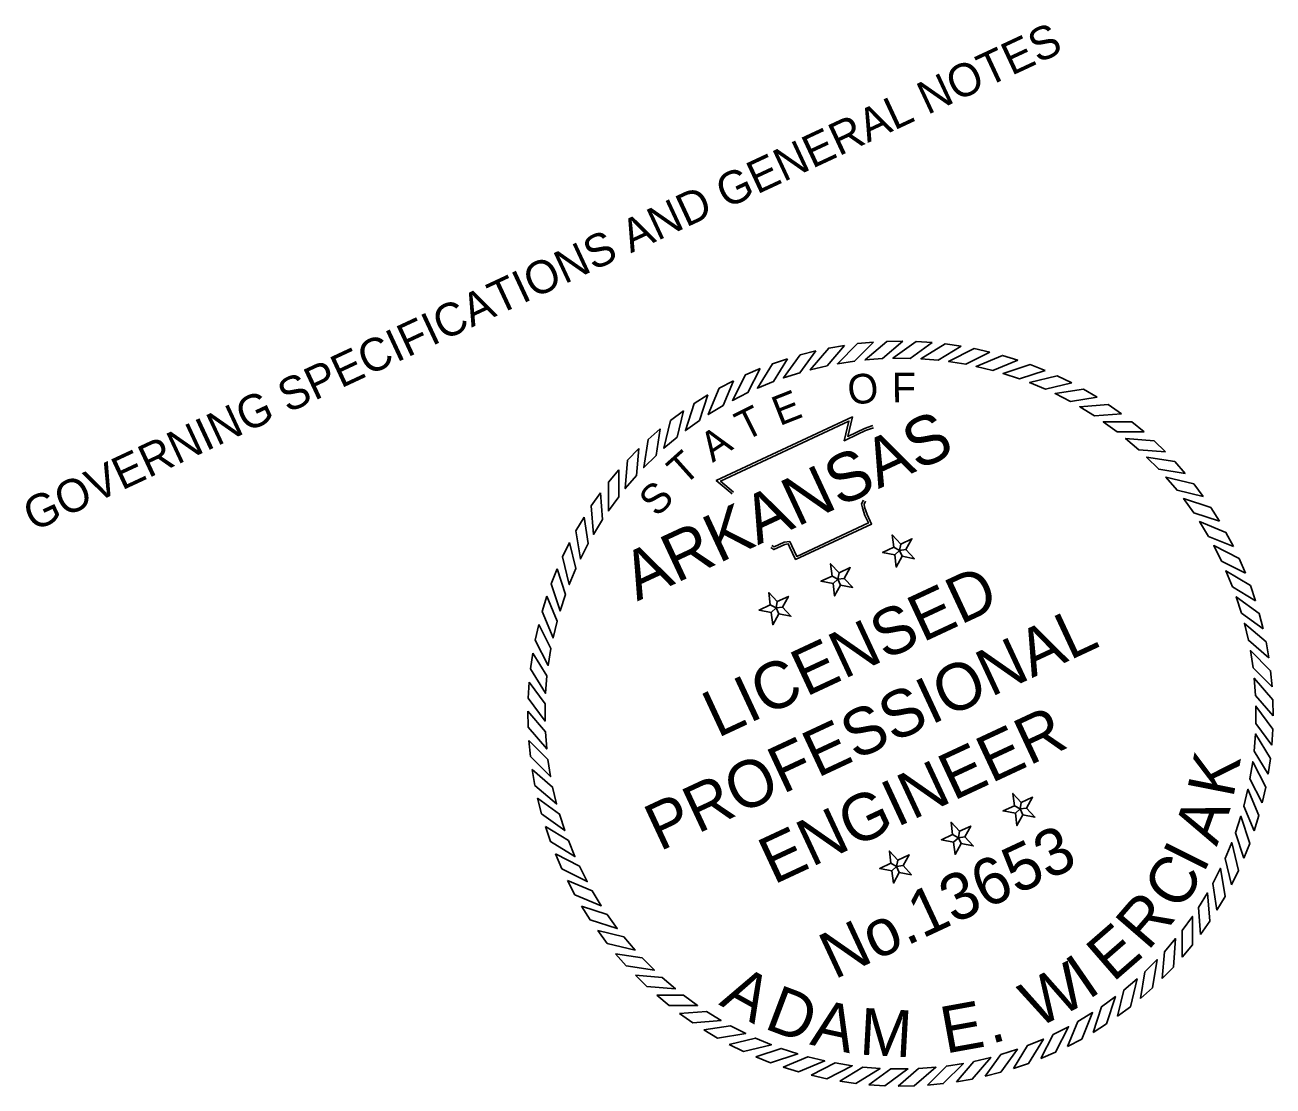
# Model space of a CAD drawing. Extents: x 756658 to 763719, y 1656413 to 1661090.
# Drawn here: x 762588.8 to 762989.5, y 1660427.5 to 1660768.4 of the extents above; entities that cross this region are included whole.
import ezdxf

# ---------------------------------------------------------------- set-up
doc = ezdxf.new("R2010")
doc.units = 0
doc.layers.add('1', color=7, linetype='Continuous')
doc.layers.add('G-ANNO-STMP-AEW', color=7, linetype='Continuous')

msp = doc.modelspace()

# ---------------------------------------------------------------- linework, layer by layer
at = {"layer": 'G-ANNO-STMP-AEW'}
for points in [[(762861.26, 1660666.49), (762856.14, 1660666), (762849.66, 1660659.52), (762855.15, 1660660.37)], [(762870.65, 1660666.79), (762865.51, 1660666.72), (762858.54, 1660660.76), (762864.08, 1660661.18)], [(762880.04, 1660666.37), (762874.9, 1660666.69), (762867.48, 1660661.3), (762873.04, 1660661.28)], [(762842.71, 1660663.67), (762837.72, 1660662.39), (762832.33, 1660654.97), (762837.62, 1660656.67)], [(762851.93, 1660665.44), (762846.86, 1660664.56), (762840.91, 1660657.59), (762846.32, 1660658.87)], [(762889.36, 1660665.2), (762884.26, 1660665.93), (762876.45, 1660661.14), (762881.99, 1660660.69)], [(762898.56, 1660663.31), (762893.54, 1660664.44), (762885.37, 1660660.27), (762890.86, 1660659.39)], [(762833.65, 1660661.17), (762828.78, 1660659.51), (762823.99, 1660651.69), (762829.13, 1660653.8)], [(762907.58, 1660660.71), (762902.67, 1660662.22), (762894.2, 1660658.71), (762899.6, 1660657.4)], [(762916.37, 1660657.4), (762911.59, 1660659.3), (762902.87, 1660656.46), (762908.15, 1660654.73)], [(762824.82, 1660657.98), (762820.09, 1660655.94), (762815.93, 1660647.77), (762820.89, 1660650.27)], [(762924.88, 1660653.41), (762920.26, 1660655.68), (762911.35, 1660653.54), (762916.47, 1660651.39)], [(762816.26, 1660654.1), (762811.71, 1660651.69), (762808.2, 1660643.22), (762812.95, 1660646.11)], [(762933.05, 1660648.77), (762928.62, 1660651.39), (762919.56, 1660649.96), (762924.51, 1660647.42)], [(762808.04, 1660649.56), (762803.69, 1660646.81), (762800.86, 1660638.09), (762805.36, 1660641.34)], [(762940.82, 1660643.5), (762936.62, 1660646.46), (762927.48, 1660645.74), (762932.21, 1660642.82)], [(762800.19, 1660644.39), (762796.08, 1660641.31), (762793.94, 1660632.39), (762798.18, 1660635.99)], [(762792.78, 1660638.62), (762788.92, 1660635.22), (762787.48, 1660626.17), (762791.43, 1660630.08)], [(762948.16, 1660637.64), (762944.2, 1660640.92), (762935.03, 1660640.92), (762939.52, 1660637.64)], [(762955.02, 1660631.22), (762951.33, 1660634.8), (762942.19, 1660635.52), (762946.4, 1660631.9)], [(762785.84, 1660632.29), (762782.26, 1660628.6), (762781.54, 1660619.46), (762785.16, 1660623.67)], [(762961.35, 1660624.28), (762957.95, 1660628.14), (762948.9, 1660629.58), (762952.81, 1660625.64)], [(762779.42, 1660625.43), (762776.14, 1660621.47), (762776.14, 1660612.3), (762779.42, 1660616.79)], [(762967.12, 1660616.87), (762964.04, 1660620.99), (762955.12, 1660623.13), (762958.72, 1660618.89)], [(762773.56, 1660618.09), (762770.6, 1660613.89), (762771.32, 1660604.75), (762774.24, 1660609.48)], [(762972.29, 1660609.03), (762969.54, 1660613.37), (762960.82, 1660616.21), (762964.07, 1660611.7)], [(762768.29, 1660610.32), (762765.67, 1660605.89), (762767.11, 1660596.83), (762769.65, 1660601.78)], [(762976.83, 1660600.8), (762974.42, 1660605.35), (762965.95, 1660608.86), (762968.84, 1660604.11)], [(762869.59, 1660599.59), (762869.99, 1660601.64), (762867.28, 1660604.54), (762867.76, 1660600.6)], [(762869.59, 1660599.59), (762871.66, 1660599.84), (762873.59, 1660603.32), (762869.99, 1660601.64)], [(762763.65, 1660602.15), (762761.39, 1660597.53), (762763.53, 1660588.62), (762765.67, 1660593.74)], [(762869.59, 1660599.59), (762867.76, 1660600.6), (762864.16, 1660598.92), (762868.06, 1660598.16)], [(762869.59, 1660599.59), (762868.06, 1660598.16), (762868.55, 1660594.22), (762870.47, 1660597.69)], [(762869.59, 1660599.59), (762870.47, 1660597.69), (762874.37, 1660596.93), (762871.66, 1660599.84)], [(762980.71, 1660592.25), (762978.67, 1660596.97), (762970.5, 1660601.13), (762973, 1660596.17)], [(762849.76, 1660590.34), (762850.16, 1660592.39), (762847.45, 1660595.3), (762847.94, 1660591.35)], [(762759.66, 1660593.65), (762757.77, 1660588.86), (762760.6, 1660580.14), (762762.34, 1660585.42)], [(762849.76, 1660590.34), (762847.94, 1660591.35), (762844.34, 1660589.67), (762848.24, 1660588.92)], [(762849.76, 1660590.34), (762848.24, 1660588.92), (762848.72, 1660584.97), (762850.65, 1660588.45)], [(762849.76, 1660590.34), (762851.84, 1660590.6), (762853.76, 1660594.07), (762850.16, 1660592.39)], [(762849.76, 1660590.34), (762850.65, 1660588.45), (762854.55, 1660587.69), (762851.84, 1660590.6)], [(762983.9, 1660583.41), (762982.24, 1660588.28), (762974.42, 1660593.07), (762976.53, 1660587.93)], [(762756.36, 1660584.85), (762754.84, 1660579.94), (762758.35, 1660571.47), (762759.67, 1660576.87)], [(762829.94, 1660581.1), (762830.34, 1660583.15), (762827.63, 1660586.05), (762828.11, 1660582.11)], [(762829.94, 1660581.1), (762832.01, 1660581.35), (762833.94, 1660584.83), (762830.34, 1660583.15)], [(762986.4, 1660574.36), (762985.12, 1660579.34), (762977.7, 1660584.73), (762979.4, 1660579.44)], [(762829.94, 1660581.1), (762828.11, 1660582.11), (762824.51, 1660580.43), (762828.41, 1660579.67)], [(762829.94, 1660581.1), (762828.41, 1660579.67), (762828.9, 1660575.73), (762830.82, 1660579.2)], [(762829.94, 1660581.1), (762830.82, 1660579.2), (762834.72, 1660578.44), (762832.01, 1660581.35)], [(762753.75, 1660575.83), (762752.63, 1660570.81), (762756.79, 1660562.64), (762757.68, 1660568.13)], [(762988.17, 1660565.13), (762987.29, 1660570.2), (762980.32, 1660576.16), (762981.6, 1660570.75)], [(762751.86, 1660566.63), (762751.13, 1660561.54), (762755.92, 1660553.72), (762756.38, 1660559.26)], [(762989.21, 1660555.8), (762988.73, 1660560.92), (762982.25, 1660567.4), (762983.1, 1660561.91)], [(762989.52, 1660546.41), (762989.45, 1660551.55), (762983.49, 1660558.53), (762983.91, 1660552.98)], [(762750.7, 1660557.31), (762750.37, 1660552.17), (762755.76, 1660544.75), (762755.78, 1660550.31)], [(762750.27, 1660547.92), (762750.35, 1660542.78), (762756.3, 1660535.81), (762755.88, 1660541.35)], [(762989.1, 1660537.03), (762989.42, 1660542.16), (762984.03, 1660549.58), (762984.01, 1660544.02)], [(762750.58, 1660538.54), (762751.06, 1660533.41), (762757.54, 1660526.93), (762756.69, 1660532.42)], [(762987.93, 1660527.71), (762988.66, 1660532.8), (762983.87, 1660540.62), (762983.42, 1660535.08)], [(762986.04, 1660518.51), (762987.17, 1660523.53), (762983, 1660531.7), (762982.12, 1660526.21)], [(762751.62, 1660529.2), (762752.51, 1660524.13), (762759.48, 1660518.18), (762758.2, 1660523.59)], [(762983.44, 1660509.48), (762984.95, 1660514.4), (762981.44, 1660522.87), (762980.13, 1660517.47)], [(762753.4, 1660519.98), (762754.67, 1660514.99), (762762.09, 1660509.6), (762760.39, 1660514.89)], [(762908.3, 1660516.57), (762908.7, 1660518.62), (762905.99, 1660521.52), (762906.48, 1660517.58)], [(762908.3, 1660516.57), (762910.38, 1660516.82), (762912.3, 1660520.3), (762908.7, 1660518.62)], [(762908.3, 1660516.57), (762906.48, 1660517.58), (762902.87, 1660515.9), (762906.78, 1660515.14)], [(762908.3, 1660516.57), (762906.78, 1660515.14), (762907.26, 1660511.2), (762909.19, 1660514.67)], [(762908.3, 1660516.57), (762909.19, 1660514.67), (762913.09, 1660513.91), (762910.38, 1660516.82)], [(762980.13, 1660500.69), (762982.02, 1660505.47), (762979.19, 1660514.19), (762977.46, 1660508.91)], [(762755.89, 1660510.92), (762757.55, 1660506.05), (762765.37, 1660501.26), (762763.26, 1660506.4)], [(762888.48, 1660507.32), (762888.88, 1660509.37), (762886.17, 1660512.28), (762886.65, 1660508.33)], [(762888.48, 1660507.32), (762890.55, 1660507.58), (762892.48, 1660511.05), (762888.88, 1660509.37)], [(762888.48, 1660507.32), (762886.65, 1660508.33), (762883.05, 1660506.65), (762886.95, 1660505.9)], [(762888.48, 1660507.32), (762886.95, 1660505.9), (762887.43, 1660501.95), (762889.36, 1660505.43)], [(762888.48, 1660507.32), (762889.36, 1660505.43), (762893.26, 1660504.67), (762890.55, 1660507.58)], [(762759.09, 1660502.09), (762761.13, 1660497.36), (762769.3, 1660493.2), (762766.79, 1660498.16)], [(762868.65, 1660498.08), (762869.05, 1660500.13), (762866.34, 1660503.03), (762866.82, 1660499.09)], [(762976.14, 1660492.18), (762978.41, 1660496.8), (762976.27, 1660505.72), (762974.12, 1660500.59)], [(762868.65, 1660498.08), (762866.82, 1660499.09), (762863.22, 1660497.41), (762867.12, 1660496.65)], [(762868.65, 1660498.08), (762867.12, 1660496.65), (762867.61, 1660492.71), (762869.53, 1660496.18)], [(762868.65, 1660498.08), (762870.72, 1660498.33), (762872.65, 1660501.81), (762869.05, 1660500.13)], [(762868.65, 1660498.08), (762869.53, 1660496.18), (762873.43, 1660495.42), (762870.72, 1660498.33)], [(762971.5, 1660484.02), (762974.12, 1660488.44), (762972.69, 1660497.5), (762970.15, 1660492.56)], [(762762.96, 1660493.53), (762765.37, 1660488.98), (762773.84, 1660485.47), (762770.95, 1660490.22)], [(762966.23, 1660476.24), (762969.19, 1660480.45), (762968.47, 1660489.59), (762965.55, 1660484.86)], [(762767.5, 1660485.31), (762770.26, 1660480.96), (762778.98, 1660478.13), (762775.72, 1660482.64)], [(762960.37, 1660468.9), (762963.65, 1660472.86), (762963.65, 1660482.03), (762960.37, 1660477.55)], [(762772.67, 1660477.46), (762775.76, 1660473.35), (762784.67, 1660471.21), (762781.08, 1660475.45)], [(762953.95, 1660462.04), (762957.53, 1660465.74), (762958.25, 1660474.88), (762954.63, 1660470.66)], [(762778.44, 1660470.05), (762781.84, 1660466.19), (762790.9, 1660464.76), (762786.98, 1660468.7)], [(762947.01, 1660455.71), (762950.87, 1660459.11), (762952.31, 1660468.17), (762948.37, 1660464.25)], [(762784.77, 1660463.11), (762788.46, 1660459.53), (762797.61, 1660458.81), (762793.39, 1660462.43)], [(762939.6, 1660449.94), (762943.72, 1660453.03), (762945.86, 1660461.94), (762941.62, 1660458.35)], [(762791.63, 1660456.69), (762795.59, 1660453.41), (762804.76, 1660453.41), (762800.28, 1660456.69)], [(762931.76, 1660444.77), (762936.1, 1660447.53), (762938.94, 1660456.25), (762934.43, 1660453)], [(762798.97, 1660450.83), (762803.18, 1660447.87), (762812.32, 1660448.59), (762807.59, 1660451.51)], [(762923.53, 1660440.23), (762928.08, 1660442.64), (762931.59, 1660451.11), (762926.84, 1660448.22)], [(762806.75, 1660445.56), (762811.17, 1660442.94), (762820.23, 1660444.38), (762815.29, 1660446.92)], [(762914.98, 1660436.36), (762919.7, 1660438.4), (762923.86, 1660446.57), (762918.9, 1660444.06)], [(762814.91, 1660440.92), (762819.53, 1660438.66), (762828.45, 1660440.8), (762823.32, 1660442.94)], [(762906.14, 1660433.16), (762911.01, 1660434.82), (762915.8, 1660442.64), (762910.66, 1660440.53)], [(762823.42, 1660436.94), (762828.2, 1660435.04), (762836.92, 1660437.87), (762831.64, 1660439.61)], [(762897.09, 1660430.67), (762902.07, 1660431.95), (762907.46, 1660439.36), (762902.17, 1660437.66)], [(762832.21, 1660433.63), (762837.13, 1660432.11), (762845.6, 1660435.62), (762840.2, 1660436.94)], [(762841.23, 1660431.02), (762846.25, 1660429.9), (762854.42, 1660434.06), (762848.94, 1660434.95)], [(762878.53, 1660427.85), (762883.65, 1660428.33), (762890.13, 1660434.81), (762884.64, 1660433.96)], [(762887.86, 1660428.89), (762892.93, 1660429.78), (762898.89, 1660436.75), (762893.48, 1660435.47)], [(762850.44, 1660429.13), (762855.53, 1660428.4), (762863.35, 1660433.19), (762857.81, 1660433.65)], [(762859.76, 1660427.97), (762864.89, 1660427.64), (762872.31, 1660433.03), (762866.75, 1660433.05)], [(762869.14, 1660427.54), (762874.28, 1660427.62), (762881.26, 1660433.57), (762875.71, 1660433.15)]]:
    msp.add_lwpolyline(points, close=True, dxfattribs=at)
for points in [[(762815.83, 1660617.76), (762810.75, 1660622.05), (762854.47, 1660642.47), (762852.96, 1660636.18), (762855.91, 1660637.6), (762858.38, 1660638.79), (762860.98, 1660639.68)], [(762816.33, 1660618.34), (762812.16, 1660621.87), (762853.36, 1660641.11), (762851.84, 1660634.79), (762856.24, 1660636.91), (762858.67, 1660638.08), (762861.23, 1660638.95)], [(762858.69, 1660615.43), (762858.23, 1660614.48), (762858.4, 1660613.46), (762859.21, 1660611.07), (762860.62, 1660608.05), (762836.21, 1660596.67), (762834.31, 1660600.75), (762833.89, 1660601.65), (762832.75, 1660601.49), (762829.28, 1660599.87), (762828.23, 1660600.53)], [(762858, 1660615.77), (762857.43, 1660614.59), (762857.66, 1660613.27), (762858.5, 1660610.79), (762859.61, 1660608.42), (762836.58, 1660597.68), (762835, 1660601.07), (762834.34, 1660602.49), (762832.53, 1660602.24), (762829.33, 1660600.74), (762828.63, 1660601.18)]]:
    msp.add_lwpolyline(points, dxfattribs=at)

# ---------------------------------------------------------------- texts
at = {"layer": '1'}
msp.add_text('GOVERNING SPECIFICATIONS AND GENERAL NOTES', height=10.5516, rotation=25, dxfattribs=at).set_placement((762591.47, 1660605.52))
at = {"layer": 'G-ANNO-STMP-AEW'}
for s, height, rotation, p in [('O', 9.52, 6.2218, (762853.42, 1660646.27)), ('F', 9.52, 0.3628, (762867.16, 1660647.15)), ('E', 9.52, 21.672, (762831.09, 1660639.46)), ('T', 9.52, 26.4789, (762819.93, 1660634.58)), ('ARKANSAS', 15.535, 25, (762785.37, 1660583.16)), ('A', 9.52, 33.6788, (762809.59, 1660627.66)), ('T', 9.52, 41.9015, (762800.39, 1660620.05)), ('S', 9.52, 44.7726, (762791.72, 1660610.01)), ('LICENSED', 15.039, 25, (762811.17, 1660539.24)), ('PROFESSIONAL', 15.0392, 25, (762792.59, 1660502.82)), ('ENGINEER', 15.039, 25, (762829.18, 1660492.13)), ('K', 15.04, 78.8471, (762976.68, 1660519.74)), ('A', 15.04, 70.185, (762971.44, 1660504.28)), ('No.13653', 14.98, 25, (762848.64, 1660461.65)), ('I', 15.04, 63.4057, (762967.15, 1660495.53)), ('C', 15.04, 57.1396, (762959.68, 1660483.29)), ('R', 15.04, 49.1616, (762949.3, 1660470.7)), ('E', 15.04, 41.0125, (762938.15, 1660460.65)), ('W', 15.04, 27.1127, (762913.61, 1660445.89)), ('I', 15.04, 34.5753, (762930.19, 1660455.04)), ('A', 15.04, 330.982, (762811.32, 1660453.79)), ('D', 15.04, 339.3022, (762825.75, 1660446.18)), ('A', 15.04, 347.6223, (762840.51, 1660440.92)), ('E', 15.04, 10.2782, (762884.35, 1660437.92)), ('M', 15.04, 356.7969, (762856.51, 1660437.67)), ('.', 15.04, 15.8583, (762899.02, 1660441.01))]:
    msp.add_text(s, height=height, rotation=rotation, dxfattribs=at).set_placement(p)

doc.saveas('drawing.dxf')
